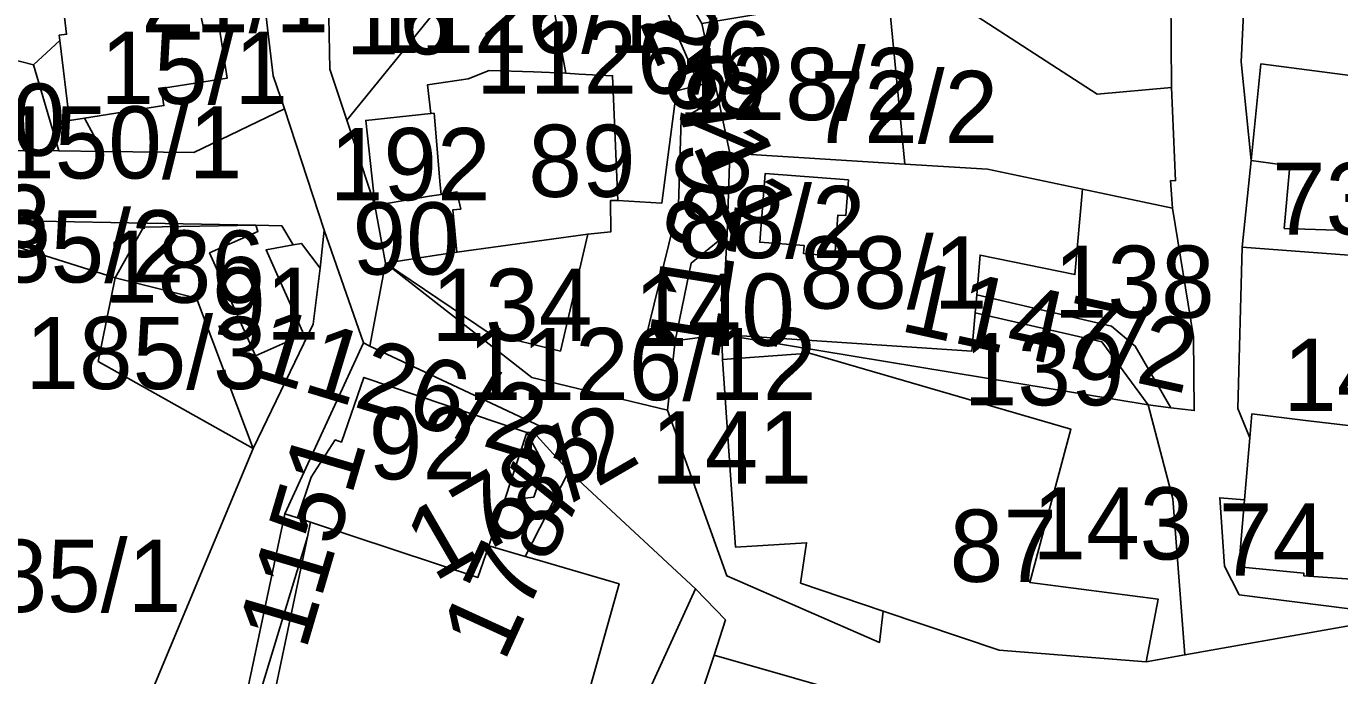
# Model space of a CAD drawing. Extents: x -623250 to -619626, y -1079612 to -1075424.
# Drawn here: x -621601 to -621418.9, y -1077535.8 to -1077445.8 of the extents above; entities that cross this region are included whole.
import ezdxf

# ---------------------------------------------------------------- set-up
doc = ezdxf.new("R2010")
doc.units = 0
doc.layers.add('Parcela nároku', color=7, linetype='Continuous')
doc.layers.add('Parcelní číslo', color=7, linetype='Continuous')

msp = doc.modelspace()

# ---------------------------------------------------------------- linework, layer by layer
at = {"layer": 'Parcela nároku'}
for points in [[(-621451.75, -1077423), (-621466.76, -1077425.29), (-621469.29, -1077425.7), (-621468.9, -1077428.12), (-621476.98, -1077429.42), (-621475.26, -1077440.11), (-621471.93, -1077440.18), (-621471.5, -1077442.95), (-621452.51, -1077455.2), (-621442.23, -1077454.31), (-621442.3, -1077441.52), (-621444.35, -1077441.74), (-621449.46, -1077428.7), (-621450.93, -1077425.2)], [(-621651.71, -1077428.55), (-621625.29, -1077427.92), (-621608.27, -1077430.64), (-621590.81, -1077425.21), (-621596.41, -1077438.29), (-621595.37, -1077446.92), (-621596.41, -1077447.05), (-621596.32, -1077447.8), (-621599.98, -1077451.17), (-621607.92, -1077449.11), (-621609.14, -1077444.92), (-621615.21, -1077439.45), (-621626.72, -1077438.85), (-621649.84, -1077437.65)], [(-621431.19, -1077464.42), (-621432.42, -1077476.42), (-621394.2, -1077479.27), (-621389.22, -1077446.41), (-621387.12, -1077432.52), (-621431.55, -1077429.78), (-621432.54, -1077450.72)], [(-621547.56, -1077449.24), (-621547.71, -1077447.97), (-621544.37, -1077443.86), (-621543.01, -1077443.69), (-621543.93, -1077436.2), (-621548.94, -1077436.76), (-621548.97, -1077436.47), (-621554.97, -1077437.15), (-621559.23, -1077434.88), (-621558.89, -1077451.75), (-621556.54, -1077458.83), (-621548.86, -1077449.39)], [(-621523.62, -1077440.31), (-621513.83, -1077439.85), (-621507.7, -1077453.97), (-621510.81, -1077454.77), (-621512.86, -1077470.31), (-621518.98, -1077469.95), (-621519.69, -1077452.67), (-621524.33, -1077452.43), (-621526.15, -1077452.32), (-621528.22, -1077441.35)], [(-621507.3, -1077445.44), (-621505.58, -1077453.42), (-621507.7, -1077453.97), (-621513.83, -1077439.85), (-621510.57, -1077439.83)], [(-621507.3, -1077445.44), (-621481.49, -1077441.1), (-621479.17, -1077464.9), (-621503.43, -1077463.41), (-621505.07, -1077455.79), (-621505.58, -1077453.42)], [(-621442.07, -1077471), (-621442.35, -1077467.18), (-621441.68, -1077467.22), (-621442.23, -1077454.31), (-621452.51, -1077455.2), (-621471.5, -1077442.95), (-621471.93, -1077440.18), (-621475.26, -1077440.11), (-621481.49, -1077441.1), (-621479.17, -1077464.9), (-621467.73, -1077465.6), (-621454.56, -1077468.37)], [(-621596.32, -1077447.8), (-621594.98, -1077458.86), (-621592.89, -1077458.53), (-621590.42, -1077463.16), (-621596.47, -1077463.09), (-621599.98, -1077451.17)], [(-621607.92, -1077449.11), (-621599.98, -1077451.17), (-621596.47, -1077463.09), (-621603.87, -1077463), (-621606.45, -1077454.16), (-621607.32, -1077451.17)], [(-621545.36, -1077453.93), (-621539.72, -1077453.09), (-621536.81, -1077451.95), (-621530.66, -1077452.12), (-621526.15, -1077452.32), (-621524.33, -1077452.43), (-621519.69, -1077452.67), (-621518.98, -1077469.95), (-621519.99, -1077469.97), (-621519.92, -1077474.27), (-621523.13, -1077474.6), (-621541.27, -1077477.11), (-621541.83, -1077471.24), (-621540.74, -1077471.13), (-621541.26, -1077468.73), (-621543.45, -1077469.1), (-621543.58, -1077467.76), (-621544.44, -1077457.86), (-621544.87, -1077457.91)], [(-621411.07, -1077453.45), (-621429.81, -1077451.02), (-621431.19, -1077464.42), (-621425.79, -1077465.14), (-621426.59, -1077473.81), (-621412.19, -1077474.29)], [(-621431.19, -1077464.42), (-621425.79, -1077465.14), (-621426.59, -1077473.81), (-621412.19, -1077474.29), (-621411.07, -1077453.45), (-621429.81, -1077451.02)], [(-621512.86, -1077470.31), (-621518.98, -1077469.95), (-621519.99, -1077469.97), (-621519.92, -1077474.27), (-621523.13, -1077474.6), (-621526.93, -1077490.82), (-621536.67, -1077488.42), (-621551.16, -1077478.62), (-621530.89, -1077494.49), (-621512.1, -1077498.99), (-621511.02, -1077489.41), (-621515.25, -1077489.73), (-621510.54, -1077470.55), (-621510.2, -1077458.69), (-621505.07, -1077455.79), (-621505.58, -1077453.42), (-621507.7, -1077453.97), (-621510.81, -1077454.77)], [(-621510.54, -1077470.55), (-621510.2, -1077458.69), (-621505.07, -1077455.79), (-621503.43, -1077463.41), (-621503.83, -1077474.55), (-621508.78, -1077478.61), (-621511.02, -1077489.41), (-621515.25, -1077489.73)], [(-621544.87, -1077457.91), (-621544.44, -1077457.86), (-621543.58, -1077467.76), (-621543.45, -1077469.1), (-621545.07, -1077469.37), (-621552.63, -1077470.66), (-621552.84, -1077468.65), (-621553.9, -1077458.85)], [(-621467.73, -1077465.6), (-621479.17, -1077464.9), (-621503.43, -1077463.41), (-621503.83, -1077474.55), (-621504.55, -1077488.53), (-621469.89, -1077490.83), (-621469.43, -1077485.49), (-621469.22, -1077483.03), (-621468.75, -1077477.52), (-621455.6, -1077480.22), (-621454.56, -1077468.37)], [(-621487.36, -1077472.05), (-621486.99, -1077467.1), (-621498.55, -1077466.23), (-621499.3, -1077475.73), (-621493.13, -1077476.2), (-621493.21, -1077477.31), (-621488.89, -1077477.64), (-621488.46, -1077471.96)], [(-621486.99, -1077467.1), (-621498.55, -1077466.23), (-621499.3, -1077475.73), (-621493.13, -1077476.2), (-621493.21, -1077477.31), (-621488.89, -1077477.64), (-621488.46, -1077471.96), (-621487.36, -1077472.05)], [(-621442.07, -1077471), (-621439.15, -1077488.83), (-621439.05, -1077499.06), (-621442.31, -1077498.65), (-621447.23, -1077490.12), (-621450.51, -1077487.38), (-621469.22, -1077483.03), (-621468.75, -1077477.52), (-621455.6, -1077480.22), (-621454.56, -1077468.37)], [(-621543.45, -1077469.1), (-621541.26, -1077468.73), (-621540.74, -1077471.13), (-621541.83, -1077471.24), (-621541.27, -1077477.11), (-621544.12, -1077477.54), (-621551.16, -1077478.62), (-621552.63, -1077470.66), (-621545.07, -1077469.37)], [(-621614.41, -1077472.53), (-621569.13, -1077473.38), (-621584.71, -1077473.65), (-621588.64, -1077480.64)], [(-621560.22, -1077479.34), (-621562.82, -1077475.89), (-621563.99, -1077476.1), (-621567.72, -1077476.79), (-621562.51, -1077488.51), (-621563.36, -1077488.89), (-621569.2, -1077491.48), (-621575.55, -1077477.22), (-621569.69, -1077474.61), (-621568.85, -1077474.24), (-621569.13, -1077473.38), (-621584.71, -1077473.65), (-621588.64, -1077480.64), (-621577.36, -1077483.49), (-621569.52, -1077504.32), (-621561.19, -1077487.1)], [(-621565.52, -1077473.48), (-621563.99, -1077476.1), (-621567.72, -1077476.79), (-621562.51, -1077488.51), (-621563.36, -1077488.89), (-621569.2, -1077491.48), (-621575.55, -1077477.22), (-621569.69, -1077474.61), (-621568.85, -1077474.24), (-621569.13, -1077473.38)], [(-621544.12, -1077477.54), (-621541.27, -1077477.11), (-621523.13, -1077474.6), (-621526.93, -1077490.82), (-621536.67, -1077488.42), (-621551.16, -1077478.62)], [(-621508.78, -1077478.61), (-621503.83, -1077474.55), (-621504.55, -1077488.53), (-621511.02, -1077489.41)], [(-621432.87, -1077520.7), (-621423.85, -1077521.6), (-621423.86, -1077521.97), (-621413.99, -1077522.64), (-621413.07, -1077514.1), (-621411.75, -1077501.83), (-621423.64, -1077500.41), (-621431.06, -1077499.52), (-621431.34, -1077502.84), (-621433.01, -1077498.77), (-621432.42, -1077476.42), (-621394.2, -1077479.27), (-621394.64, -1077484.28), (-621398.13, -1077523.76), (-621398.59, -1077528.92), (-621409.83, -1077527.49), (-621432.82, -1077524.57), (-621434.85, -1077520.63), (-621435.53, -1077511.12), (-621432.08, -1077511.42)], [(-621588.64, -1077480.64), (-621590.99, -1077492.25), (-621569.52, -1077504.32), (-621577.36, -1077483.49)], [(-621469.22, -1077483.03), (-621450.51, -1077487.38), (-621447.23, -1077490.12), (-621442.31, -1077498.65), (-621445.44, -1077498.26), (-621451.88, -1077489.51), (-621469.43, -1077485.49)], [(-621451.88, -1077489.51), (-621469.43, -1077485.49), (-621469.89, -1077490.83), (-621504.55, -1077488.53), (-621445.44, -1077498.26)], [(-621565.12, -1077513.35), (-621554.23, -1077489.68), (-621553.33, -1077490.11), (-621528.85, -1077501.64), (-621530.63, -1077502.07), (-621531.58, -1077502.07), (-621554.15, -1077494.47), (-621557.27, -1077503.42), (-621558.13, -1077503.11), (-621561.45, -1077508.27), (-621563.38, -1077513.93)], [(-621493.64, -1077522.95), (-621482.17, -1077526.82), (-621482.69, -1077531.18), (-621503.86, -1077521.94), (-621512.1, -1077498.99), (-621511.02, -1077489.41), (-621504.55, -1077488.53), (-621504.46, -1077492), (-621502.67, -1077517.96), (-621492.79, -1077517.37)], [(-621461.86, -1077522.86), (-621456.15, -1077501.64), (-621492.39, -1077491.11), (-621504.46, -1077492), (-621504.55, -1077488.53), (-621445.44, -1077498.26), (-621442.04, -1077511.26), (-621440.35, -1077532.9), (-621445.71, -1077533.85), (-621444.07, -1077525.16)], [(-621492.79, -1077517.37), (-621493.64, -1077522.95), (-621482.17, -1077526.82), (-621466.12, -1077532.24), (-621445.71, -1077533.85), (-621444.07, -1077525.16), (-621461.86, -1077522.86), (-621456.15, -1077501.64), (-621492.39, -1077491.11), (-621504.46, -1077492), (-621502.67, -1077517.96)], [(-621557.27, -1077503.42), (-621554.15, -1077494.47), (-621531.58, -1077502.07), (-621534.68, -1077511.49), (-621536.44, -1077516.54), (-621536.83, -1077517.79), (-621538.37, -1077522.19), (-621561.57, -1077514.53), (-621563.38, -1077513.93), (-621561.45, -1077508.27), (-621558.13, -1077503.11)], [(-621432.08, -1077511.42), (-621432.87, -1077520.7), (-621423.85, -1077521.6), (-621423.86, -1077521.97), (-621413.99, -1077522.64), (-621413.07, -1077514.1), (-621411.75, -1077501.83), (-621423.64, -1077500.41), (-621431.06, -1077499.52), (-621431.34, -1077502.84)], [(-621530.63, -1077511.03), (-621534.68, -1077511.49), (-621536.44, -1077516.54), (-621536.83, -1077517.79), (-621531.8, -1077519.26), (-621525.77, -1077507.45), (-621530.63, -1077502.07), (-621531.58, -1077502.07), (-621529.12, -1077506.65)], [(-621531.58, -1077502.07), (-621529.12, -1077506.65), (-621530.63, -1077511.03), (-621534.68, -1077511.49)], [(-621570.02, -1077554.44), (-621540.57, -1077563.79), (-621537.5, -1077553.48), (-621532.75, -1077554.94), (-621528.1, -1077556.37), (-621518.79, -1077523.05), (-621530.13, -1077519.75), (-621531.8, -1077519.26), (-621525.77, -1077507.45), (-621508.19, -1077523.73), (-621527.12, -1077565.22), (-621534.26, -1077633.61), (-621575.49, -1077614.16), (-621573.12, -1077605.67), (-621569.74, -1077606.33), (-621554.16, -1077562.06), (-621558.2, -1077561.44), (-621574.58, -1077558.02), (-621561.99, -1077516.53), (-621567.79, -1077544.18)], [(-621563.38, -1077513.93), (-621561.57, -1077514.53), (-621561.99, -1077516.53), (-621574.58, -1077558.02), (-621565.12, -1077513.35)], [(-621536.83, -1077517.79), (-621538.37, -1077522.19), (-621561.57, -1077514.53), (-621561.99, -1077516.53), (-621567.79, -1077544.18), (-621570.02, -1077554.44), (-621540.57, -1077563.79), (-621537.5, -1077553.48), (-621532.75, -1077554.94), (-621528.1, -1077556.37), (-621518.79, -1077523.05), (-621530.13, -1077519.75), (-621531.8, -1077519.26)], [(-621491.25, -1077565.09), (-621489.79, -1077560.14), (-621488.72, -1077560.46), (-621486.86, -1077554.73), (-621489.61, -1077553.89), (-621489.07, -1077552.2), (-621490.85, -1077551.64), (-621485.61, -1077547.09), (-621483.32, -1077539.3), (-621472.27, -1077542.46), (-621489.38, -1077588.03), (-621501.26, -1077644.07), (-621534.26, -1077633.61), (-621527.12, -1077565.22), (-621508.19, -1077523.73), (-621504.04, -1077528.05), (-621505.63, -1077532.93), (-621515.9, -1077564.01), (-621508.14, -1077566.67), (-621502.05, -1077561.37), (-621495.62, -1077563.28), (-621495.76, -1077563.75)], [(-621495.76, -1077563.75), (-621495.62, -1077563.28), (-621502.05, -1077561.37), (-621508.14, -1077566.67), (-621515.9, -1077564.01), (-621505.63, -1077532.93), (-621483.32, -1077539.3), (-621485.61, -1077547.09), (-621490.85, -1077551.64), (-621489.07, -1077552.2), (-621489.61, -1077553.89), (-621486.86, -1077554.73), (-621488.72, -1077560.46), (-621489.79, -1077560.14), (-621491.25, -1077565.09)]]:
    msp.add_lwpolyline(points, close=True, dxfattribs=at)
for points in [[(-621442.3, -1077441.52), (-621442.23, -1077454.31), (-621441.68, -1077467.22), (-621442.35, -1077467.18), (-621442.07, -1077471), (-621439.15, -1077488.83), (-621439.05, -1077499.06), (-621442.31, -1077498.65), (-621445.44, -1077498.26), (-621442.04, -1077511.26), (-621440.35, -1077532.9), (-621409.83, -1077527.49), (-621432.82, -1077524.57), (-621434.85, -1077520.63), (-621435.53, -1077511.12), (-621432.08, -1077511.42), (-621431.34, -1077502.84), (-621433.01, -1077498.77), (-621432.42, -1077476.42), (-621431.19, -1077464.42), (-621432.54, -1077450.72), (-621431.55, -1077429.78)], [(-621568.85, -1077434.75), (-621566.72, -1077452.69), (-621565.18, -1077457.26), (-621577.75, -1077463.31), (-621590.42, -1077463.16), (-621592.89, -1077458.53), (-621581.88, -1077456.81), (-621582.21, -1077454.73), (-621582.25, -1077454.43), (-621573.11, -1077453), (-621574.18, -1077446.15), (-621576.31, -1077446.48), (-621578.01, -1077438.34)], [(-621559.23, -1077434.88), (-621558.89, -1077451.75), (-621556.54, -1077458.83), (-621552.63, -1077470.66), (-621551.16, -1077478.62), (-621553.33, -1077490.11), (-621554.23, -1077489.68), (-621559.69, -1077474.06), (-621565.18, -1077457.26), (-621566.72, -1077452.69), (-621568.85, -1077434.75)], [(-621596.41, -1077438.29), (-621595.37, -1077446.92), (-621596.41, -1077447.05), (-621596.32, -1077447.8), (-621594.98, -1077458.86), (-621592.89, -1077458.53), (-621581.88, -1077456.81), (-621582.21, -1077454.73), (-621582.25, -1077454.43), (-621573.11, -1077453), (-621574.18, -1077446.15), (-621576.31, -1077446.48), (-621578.01, -1077438.34)], [(-621528.22, -1077441.35), (-621526.15, -1077452.32), (-621530.66, -1077452.12), (-621536.81, -1077451.95), (-621539.72, -1077453.09), (-621545.36, -1077453.93), (-621544.87, -1077457.91), (-621553.9, -1077458.85), (-621552.84, -1077468.65), (-621552.63, -1077470.66), (-621556.54, -1077458.83), (-621548.86, -1077449.39), (-621547.56, -1077449.24), (-621547.71, -1077447.97), (-621544.37, -1077443.86)], [(-621603.87, -1077463), (-621596.47, -1077463.09), (-621590.42, -1077463.16), (-621577.75, -1077463.31), (-621565.18, -1077457.26), (-621559.69, -1077474.06), (-621560.22, -1077479.34), (-621562.82, -1077475.89), (-621563.99, -1077476.1), (-621565.52, -1077473.48), (-621569.13, -1077473.38), (-621614.41, -1077472.53)], [(-621585.75, -1077543.14), (-621569.52, -1077504.32), (-621590.99, -1077492.25), (-621588.64, -1077480.64), (-621614.41, -1077472.53), (-621619.97, -1077474.37), (-621638.79, -1077480.6), (-621643.71, -1077499.4), (-621665.65, -1077531.48), (-621675.33, -1077545.64)], [(-621574.58, -1077558.02), (-621565.12, -1077513.35), (-621554.23, -1077489.68), (-621559.69, -1077474.06), (-621560.22, -1077479.34), (-621561.19, -1077487.1), (-621569.52, -1077504.32), (-621585.75, -1077543.14)], [(-621483.32, -1077539.3), (-621505.63, -1077532.93), (-621504.04, -1077528.05), (-621508.19, -1077523.73), (-621525.77, -1077507.45), (-621530.63, -1077502.07), (-621528.85, -1077501.64), (-621553.33, -1077490.11), (-621551.16, -1077478.62), (-621530.89, -1077494.49), (-621512.1, -1077498.99), (-621503.86, -1077521.94), (-621482.69, -1077531.18), (-621482.17, -1077526.82), (-621466.12, -1077532.24), (-621445.71, -1077533.85), (-621440.35, -1077532.9), (-621409.83, -1077527.49)]]:
    msp.add_lwpolyline(points, dxfattribs=at)

# ---------------------------------------------------------------- texts
at = {"layer": 'Parcelní číslo'}
for s, rotation, p in [('1126/11', 293.4686, (-621522.04, -1077431.51)), ('1126/8', 80.9582, (-621505.08, -1077492.44)), ('1147/2', 347.6335, (-621480.08, -1077487.96)), ('1126/2', 343.1471, (-621570.04, -1077494.13)), ('178/2', 30.1819, (-621544.43, -1077522.88)), ('178/3', 65.4425, (-621534.73, -1077534.06)), ('1151', 73.5514, (-621562.22, -1077532.42))]:
    msp.add_text(s, height=10, rotation=rotation, dxfattribs=at).set_placement(p)
for s, p in [('21/1', (-621585.02, -1077446.64)), ('1126/1', (-621553.78, -1077449.52)), ('16', (-621556.7, -1077449.7)), ('1126/6', (-621538.61, -1077455.14)), ('15/1', (-621590.7, -1077456.56)), ('128/2', (-621510.64, -1077458.81)), ('72/2', (-621492.26, -1077461.99)), ('20', (-621610.41, -1077463.75)), ('1150/1', (-621611.91, -1077466.9)), ('89', (-621531.38, -1077469.45)), ('192', (-621558.9, -1077469.91)), ('73', (-621428.29, -1077474.7)), ('191/3', (-621631, -1077477.77)), ('88/2', (-621510.64, -1077477.93)), ('90', (-621555.75, -1077480.21)), ('185/2', (-621612.47, -1077481.3)), ('186', (-621590.2, -1077484.11)), ('88/1', (-621493.77, -1077484.92)), ('138', (-621458.54, -1077486.2)), ('91', (-621575.19, -1077489.24)), ('134', (-621544.8, -1077489.41)), ('140', (-621516.72, -1077490.09)), ('185/3', (-621601.1, -1077496.07)), ('1126/12', (-621539.76, -1077497.61)), ('139', (-621471.02, -1077498.32)), ('145', (-621426.73, -1077499.1)), ('92', (-621553.5, -1077508.58)), ('141', (-621514.37, -1077509.17)), ('143', (-621461.5, -1077519.68)), ('74', (-621435.67, -1077521.92)), ('87', (-621472.97, -1077522.78)), ('185/1', (-621612.95, -1077526.95))]:
    msp.add_text(s, height=10, dxfattribs=at).set_placement(p)

doc.saveas('drawing.dxf')
